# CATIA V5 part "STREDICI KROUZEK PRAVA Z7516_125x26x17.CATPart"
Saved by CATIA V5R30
Part number: STREDICI KROUZEK PRAVA Z7516/125x26x17
Bounding box of the stored display mesh (mm): x -4 to 13, y -62.5 to 62.5, z -62.5 to 62.5
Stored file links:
  C:\Users\ondra\Desktop\PŘÍLOHA P III\CATIA\STREDICI KROUZEK PRAVA Z7516_125x26x17.CATPart
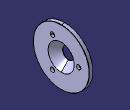
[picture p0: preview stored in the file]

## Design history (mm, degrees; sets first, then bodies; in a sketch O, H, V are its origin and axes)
Set1
  DatumSurface1 to DatumSurface37 "Z7516/12"
  Join1: Elements (DatumSurface1; DatumSurface2; DatumSurface3; DatumSurface4; DatumSurface5; DatumSurface6; DatumSurface7; DatumSurface8; DatumSurface9; DatumSurface10; DatumSurface11; DatumSurface12; DatumSurface13; DatumSurface14; DatumSurface15; DatumSurface16; DatumSurface17; DatumSurface18; DatumSurface19; DatumSurface20; DatumSurface21; DatumSurface22; DatumSurface23; DatumSurface24; DatumSurface25; DatumSurface26; DatumSurface27; DatumSurface28; DatumSurface29; DatumSurface30; DatumSurface31; DatumSurface32; DatumSurface33; DatumSurface34; DatumSurface35; DatumSurface36; DatumSurface37)
Body1 (main body)
  CloseSurface1: CloseElement Join1
  Plane1: type Offset, RefPlane yz-plane, Offset 7.3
